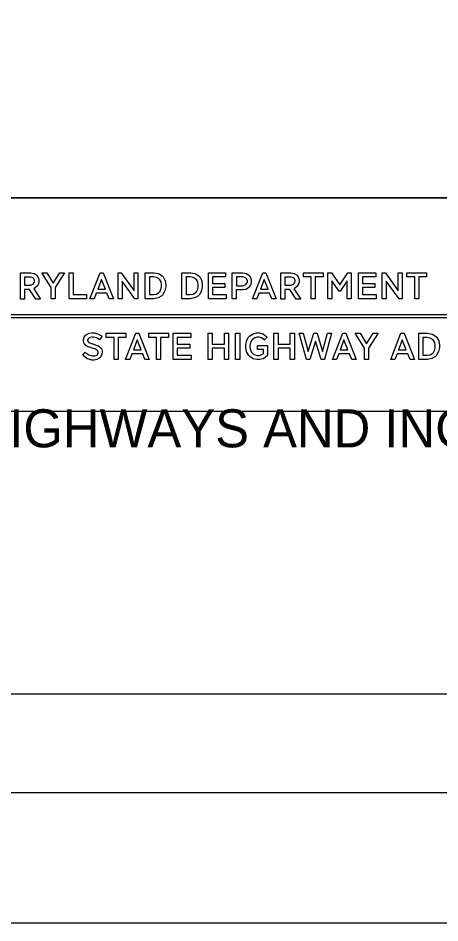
# Model space of a CAD drawing. Extents: x 12.2 to 54.5, y -7.8 to 16.1.
# Drawn here: x 51.346 to 52.376, y -7.78 to -5.573 of the extents above; entities that cross this region are included whole.
import ezdxf

# ---------------------------------------------------------------- set-up
doc = ezdxf.new("R2010")
doc.units = 0
for name, color, linetype in [('BORD-LINE', 7, 'Continuous'), ('MSHA-LOGO', 7, 'Continuous'), ('TTLB-TEXT', 7, 'Continuous'), ('USER-BORD', 7, 'Continuous'), ('USER-LINE', 7, 'Continuous')]:
    doc.layers.add(name, color=color, linetype=linetype)

msp = doc.modelspace()

# ---------------------------------------------------------------- linework, layer by layer
at = {"layer": 'BORD-LINE'}
for p, q in [((54.2173, -6.0121), (49.7444, -6.0121)), ((49.7444, -7.2211), (54.2173, -7.2211))]:
    msp.add_line(p, q, dxfattribs=at)
msp.add_lwpolyline([(46.8431, 2.8902), (54.2173, 2.8902), (54.2173, -7.4629), (46.8431, -7.4629)], close=True, dxfattribs=at)
at = {"layer": 'MSHA-LOGO'}
for points in [[(51.3519, -6.2583), (51.3519, -6.1948), (51.3742, -6.1948), (51.377, -6.1948), (51.3845, -6.1962), (51.3853, -6.1965), (51.3861, -6.1967), (51.3918, -6.2006), (51.3922, -6.2011), (51.3926, -6.2015), (51.3955, -6.2067), (51.3958, -6.2073), (51.3959, -6.2079), (51.3968, -6.2131), (51.3968, -6.2149), (51.3968, -6.2178), (51.3941, -6.2256), (51.3935, -6.2264), (51.3929, -6.2272), (51.3853, -6.233), (51.3843, -6.2333), (51.4013, -6.2586), (51.3892, -6.2586), (51.3739, -6.2353), (51.3617, -6.2353), (51.3617, -6.2586), (51.3519, -6.2586)], [(51.4367, -6.2307), (51.4367, -6.2583), (51.4269, -6.2583), (51.4269, -6.2307), (51.404, -6.1945), (51.4161, -6.1945), (51.4318, -6.2198), (51.4478, -6.1945), (51.4596, -6.1945)], [(51.4707, -6.1945), (51.4805, -6.1945), (51.4805, -6.2478), (51.5129, -6.2478), (51.5129, -6.258), (51.4707, -6.258)], [(51.5466, -6.1945), (51.5542, -6.1945), (51.579, -6.258), (51.5686, -6.258), (51.563, -6.2438), (51.5372, -6.2438), (51.5316, -6.258), (51.5218, -6.258)], [(51.6314, -6.2583), (51.6, -6.2149), (51.6, -6.2583), (51.5905, -6.2583), (51.5905, -6.1948), (51.598, -6.1948), (51.6294, -6.2382), (51.6294, -6.1948), (51.6389, -6.1948), (51.6389, -6.2583)], [(51.6569, -6.1945), (51.6746, -6.1945), (51.6784, -6.1945), (51.6886, -6.1964), (51.6897, -6.1968), (51.6907, -6.1972), (51.6991, -6.203), (51.6998, -6.2037), (51.7004, -6.2044), (51.7048, -6.2126), (51.705, -6.2136), (51.7053, -6.2145), (51.7067, -6.2227), (51.7067, -6.2254), (51.7067, -6.2287), (51.7047, -6.2385), (51.6999, -6.2475), (51.6985, -6.2491), (51.6971, -6.2506), (51.6881, -6.2557), (51.6773, -6.258), (51.6736, -6.258), (51.6569, -6.258)], [(51.7463, -6.1945), (51.7639, -6.1945), (51.7677, -6.1945), (51.7779, -6.1964), (51.779, -6.1968), (51.78, -6.1972), (51.7885, -6.203), (51.7891, -6.2037), (51.7897, -6.2044), (51.7941, -6.2126), (51.7944, -6.2136), (51.7946, -6.2145), (51.796, -6.2227), (51.796, -6.2254), (51.796, -6.2287), (51.794, -6.2385), (51.7892, -6.2475), (51.7878, -6.2491), (51.7864, -6.2506), (51.7775, -6.2557), (51.7666, -6.258), (51.763, -6.258), (51.7463, -6.258)], [(51.8108, -6.1945), (51.8529, -6.1945), (51.8529, -6.2047), (51.8206, -6.2047), (51.8206, -6.2208), (51.851, -6.2208), (51.851, -6.2307), (51.8206, -6.2307), (51.8206, -6.2474), (51.8539, -6.2474), (51.8539, -6.2576), (51.8108, -6.2576)], [(51.869, -6.2583), (51.869, -6.1948), (51.8919, -6.1948), (51.8948, -6.1948), (51.9029, -6.1962), (51.9037, -6.1965), (51.9045, -6.1968), (51.9105, -6.2009), (51.9109, -6.2014), (51.9113, -6.2019), (51.9143, -6.2074), (51.9145, -6.208), (51.9146, -6.2085), (51.9155, -6.2138), (51.9155, -6.2155), (51.9155, -6.2174), (51.9144, -6.2225), (51.9142, -6.2231), (51.9139, -6.2237), (51.9106, -6.2292), (51.9102, -6.2297), (51.9098, -6.2302), (51.9035, -6.2343), (51.9027, -6.2346), (51.9019, -6.2349), (51.8941, -6.2363), (51.8916, -6.2363), (51.8785, -6.2363), (51.8785, -6.258), (51.869, -6.258)], [(51.9439, -6.1945), (51.9515, -6.1945), (51.9763, -6.258), (51.9659, -6.258), (51.9603, -6.2442), (51.9344, -6.2442), (51.9289, -6.2583), (51.9187, -6.2583)], [(51.9875, -6.2583), (51.9875, -6.1948), (52.0097, -6.1948), (52.0125, -6.1948), (52.02, -6.1962), (52.0208, -6.1965), (52.0216, -6.1967), (52.0273, -6.2006), (52.0277, -6.2011), (52.0281, -6.2015), (52.031, -6.2067), (52.0313, -6.2073), (52.0315, -6.2079), (52.0323, -6.2131), (52.0323, -6.2149), (52.0323, -6.2178), (52.0296, -6.2256), (52.029, -6.2264), (52.0284, -6.2272), (52.0208, -6.233), (52.0198, -6.2333), (52.0369, -6.2586), (52.0248, -6.2586), (52.0094, -6.2353), (51.9973, -6.2353), (51.9973, -6.2586), (51.9875, -6.2586)], [(52.0428, -6.1945), (52.0909, -6.1945), (52.0909, -6.2047), (52.0716, -6.2047), (52.0716, -6.258), (52.0617, -6.258), (52.0617, -6.2047), (52.0428, -6.2047)], [(52.1023, -6.1945), (52.1112, -6.1945), (52.1315, -6.2241), (52.1511, -6.1945), (52.1596, -6.1945), (52.1596, -6.258), (52.1498, -6.258), (52.1498, -6.2139), (52.1324, -6.2392), (52.1298, -6.2392), (52.1121, -6.2139), (52.1121, -6.258), (52.1023, -6.258)], [(52.1773, -6.1945), (52.2195, -6.1945), (52.2195, -6.2047), (52.1871, -6.2047), (52.1871, -6.2208), (52.2175, -6.2208), (52.2175, -6.2307), (52.1871, -6.2307), (52.1871, -6.2474), (52.2205, -6.2474), (52.2205, -6.2576), (52.1773, -6.2576)], [(52.2764, -6.2583), (52.245, -6.2149), (52.245, -6.2583), (52.2355, -6.2583), (52.2355, -6.1948), (52.243, -6.1948), (52.2745, -6.2382), (52.2745, -6.1948), (52.284, -6.1948), (52.284, -6.2583)], [(52.2954, -6.1945), (52.3435, -6.1945), (52.3435, -6.2047), (52.3245, -6.2047), (52.3245, -6.258), (52.3147, -6.258), (52.3147, -6.2047), (52.2957, -6.2047), (52.2957, -6.1945)], [(51.3617, -6.205), (51.3617, -6.2244), (51.3745, -6.2244), (51.3767, -6.2244), (51.3828, -6.2222), (51.3833, -6.2218), (51.3838, -6.2214), (51.3866, -6.216), (51.3866, -6.2142), (51.3866, -6.2125), (51.3842, -6.2077), (51.3837, -6.2073), (51.3832, -6.2069), (51.3764, -6.205), (51.3742, -6.205)], [(51.5411, -6.2346), (51.5597, -6.2346), (51.5502, -6.2106)], [(51.6668, -6.205), (51.6668, -6.2478), (51.6743, -6.2478), (51.6767, -6.2478), (51.6841, -6.2463), (51.6901, -6.2428), (51.691, -6.2419), (51.6919, -6.2409), (51.6951, -6.2347), (51.6965, -6.2277), (51.6965, -6.2254), (51.6965, -6.2231), (51.6952, -6.2163), (51.6911, -6.2099), (51.6842, -6.206), (51.677, -6.2047), (51.6746, -6.2047), (51.6668, -6.2047)], [(51.7564, -6.205), (51.7564, -6.2478), (51.7639, -6.2478), (51.7664, -6.2478), (51.7738, -6.2463), (51.7797, -6.2428), (51.7806, -6.2419), (51.7815, -6.2409), (51.7848, -6.2347), (51.7862, -6.2277), (51.7862, -6.2254), (51.7862, -6.2231), (51.7848, -6.2163), (51.7808, -6.2099), (51.7739, -6.206), (51.7667, -6.2047), (51.7643, -6.2047), (51.7564, -6.2047)], [(51.8791, -6.2047), (51.8791, -6.2261), (51.8922, -6.2261), (51.8948, -6.2261), (51.9025, -6.2233), (51.906, -6.2172), (51.906, -6.2152), (51.906, -6.2132), (51.9027, -6.2073), (51.8953, -6.2047), (51.8929, -6.2047)], [(51.938, -6.2346), (51.9567, -6.2346), (51.9472, -6.2106)], [(51.9976, -6.205), (51.9976, -6.2244), (52.0104, -6.2244), (52.0126, -6.2244), (52.0186, -6.2222), (52.0192, -6.2218), (52.0197, -6.2214), (52.0225, -6.216), (52.0225, -6.2142), (52.0225, -6.2125), (52.02, -6.2077), (52.0195, -6.2073), (52.019, -6.2069), (52.0123, -6.205), (52.01, -6.205)], [(51.2136, -6.2962), (53.3302, -6.2962), (53.3302, -6.3041), (51.2136, -6.3041)], [(51.5397, -6.3835), (51.5393, -6.3832), (51.5351, -6.3805), (51.5345, -6.3803), (51.534, -6.3801), (51.5281, -6.3782), (51.5275, -6.3781), (51.5269, -6.3779), (51.5205, -6.376), (51.5199, -6.3758), (51.5192, -6.3756), (51.5134, -6.3729), (51.5128, -6.3726), (51.5122, -6.3723), (51.508, -6.3677), (51.5077, -6.3671), (51.5074, -6.3666), (51.5058, -6.3607), (51.5058, -6.3588), (51.5058, -6.357), (51.5074, -6.3518), (51.5111, -6.3468), (51.5122, -6.3459), (51.5132, -6.3451), (51.5194, -6.342), (51.5262, -6.3408), (51.5285, -6.3408), (51.5316, -6.3408), (51.5412, -6.3432), (51.5495, -6.3486), (51.5508, -6.3501), (51.5454, -6.3582), (51.5442, -6.357), (51.5375, -6.3531), (51.5305, -6.3514), (51.5282, -6.3514), (51.526, -6.3514), (51.5201, -6.353), (51.5195, -6.3533), (51.519, -6.3537), (51.516, -6.3577), (51.516, -6.3591), (51.516, -6.3604), (51.5182, -6.3639), (51.5186, -6.3643), (51.519, -6.3646), (51.5245, -6.367), (51.5253, -6.3671), (51.526, -6.3673), (51.5331, -6.3695), (51.5339, -6.3697), (51.5347, -6.3699), (51.5419, -6.3727), (51.5425, -6.3729), (51.5432, -6.3732), (51.5488, -6.3781), (51.5492, -6.3787), (51.5496, -6.3793), (51.5518, -6.3858), (51.5518, -6.388), (51.5518, -6.3899), (51.5502, -6.3956), (51.5464, -6.4009), (51.5454, -6.4018), (51.5444, -6.4027), (51.5383, -6.4059), (51.5319, -6.4073), (51.5298, -6.4073), (51.5261, -6.4073), (51.5163, -6.4046), (51.5151, -6.4041), (51.5139, -6.4035), (51.5048, -6.3965), (51.5042, -6.3957), (51.5103, -6.388), (51.5115, -6.3895), (51.5192, -6.3949), (51.5278, -6.3973), (51.5307, -6.3973), (51.5327, -6.3973), (51.5382, -6.3957), (51.5387, -6.3954), (51.5392, -6.3951), (51.5416, -6.391), (51.5416, -6.3896), (51.5416, -6.3881), (51.54, -6.3838)], [(51.5611, -6.3418), (51.6096, -6.3418), (51.6096, -6.3524), (51.5905, -6.3524), (51.5905, -6.406), (51.5806, -6.406), (51.5806, -6.352), (51.5614, -6.352), (51.5614, -6.3418)], [(51.6336, -6.3418), (51.6413, -6.3418), (51.6665, -6.406), (51.656, -6.406), (51.6505, -6.3919), (51.6243, -6.3919), (51.6189, -6.406), (51.6087, -6.406)], [(51.6649, -6.3418), (51.7135, -6.3418), (51.7135, -6.3524), (51.6943, -6.3524), (51.6943, -6.406), (51.6844, -6.406), (51.6844, -6.352), (51.6652, -6.352), (51.6652, -6.3418)], [(51.725, -6.3418), (51.7678, -6.3418), (51.7678, -6.3524), (51.7349, -6.3524), (51.7349, -6.3684), (51.7655, -6.3684), (51.7655, -6.3784), (51.7349, -6.3784), (51.7349, -6.3954), (51.7684, -6.3954), (51.7684, -6.406), (51.725, -6.406)], [(51.8499, -6.3787), (51.8199, -6.3787), (51.8199, -6.406), (51.81, -6.406), (51.81, -6.3418), (51.8199, -6.3418), (51.8199, -6.3684), (51.8499, -6.3684), (51.8499, -6.3418), (51.8598, -6.3418), (51.8598, -6.406), (51.8499, -6.406)], [(51.8774, -6.3418), (51.8873, -6.3418), (51.8873, -6.406), (51.8774, -6.406)], [(51.9304, -6.3716), (51.9553, -6.3716), (51.9553, -6.3964), (51.9547, -6.3972), (51.9464, -6.4033), (51.9454, -6.4037), (51.9444, -6.4042), (51.9356, -6.4063), (51.9326, -6.4063), (51.9296, -6.4063), (51.9204, -6.4041), (51.912, -6.3988), (51.9106, -6.3973), (51.9092, -6.3958), (51.9041, -6.3869), (51.902, -6.3769), (51.902, -6.3736), (51.902, -6.3703), (51.9041, -6.3608), (51.9089, -6.3517), (51.9103, -6.3501), (51.9117, -6.3485), (51.9199, -6.3431), (51.9285, -6.3408), (51.9314, -6.3408), (51.9347, -6.3408), (51.9437, -6.3432), (51.9448, -6.3437), (51.9457, -6.3442), (51.9535, -6.3506), (51.954, -6.3514), (51.9473, -6.3585), (51.9465, -6.3573), (51.9409, -6.3534), (51.9342, -6.3517), (51.932, -6.3517), (51.93, -6.3517), (51.9239, -6.3532), (51.9185, -6.3568), (51.9176, -6.3578), (51.9168, -6.3588), (51.9136, -6.3648), (51.9122, -6.3716), (51.9122, -6.3739), (51.9122, -6.3762), (51.9136, -6.3832), (51.917, -6.3892), (51.918, -6.3903), (51.9189, -6.3912), (51.9244, -6.3946), (51.9306, -6.396), (51.9326, -6.396), (51.9359, -6.396), (51.9449, -6.3923), (51.9457, -6.3916), (51.9457, -6.3816), (51.9304, -6.3816)], [(52.0109, -6.3787), (51.9809, -6.3787), (51.9809, -6.406), (51.971, -6.406), (51.971, -6.3418), (51.9809, -6.3418), (51.9809, -6.3684), (52.0109, -6.3684), (52.0109, -6.3418), (52.0208, -6.3418), (52.0208, -6.406), (52.0109, -6.406)], [(52.0946, -6.406), (52.0863, -6.406), (52.0723, -6.3614), (52.0585, -6.406), (52.0502, -6.406), (52.0323, -6.3418), (52.0426, -6.3418), (52.0547, -6.3861), (52.0681, -6.3418), (52.0761, -6.3418), (52.0898, -6.3861), (52.1017, -6.3418), (52.1116, -6.3418)], [(52.1387, -6.3418), (52.1464, -6.3418), (52.1717, -6.406), (52.1611, -6.406), (52.1553, -6.3919), (52.1291, -6.3919), (52.1237, -6.406), (52.1135, -6.406)], [(52.2017, -6.3781), (52.2017, -6.406), (52.1918, -6.406), (52.1918, -6.3781), (52.1688, -6.3418), (52.1812, -6.3418), (52.1972, -6.3675), (52.2135, -6.3418), (52.2253, -6.3418)], [(52.2808, -6.3418), (52.2885, -6.3418), (52.3137, -6.406), (52.3032, -6.406), (52.2977, -6.3919), (52.2716, -6.3919), (52.2661, -6.406), (52.2559, -6.406)], [(52.3249, -6.3418), (52.3428, -6.3418), (52.3465, -6.3418), (52.3568, -6.3439), (52.3578, -6.3443), (52.3589, -6.3447), (52.3674, -6.3506), (52.368, -6.3514), (52.3687, -6.3521), (52.3731, -6.3604), (52.3735, -6.3614), (52.3738, -6.3623), (52.3751, -6.3705), (52.3751, -6.3732), (52.3751, -6.3765), (52.3729, -6.3864), (52.3681, -6.3955), (52.3668, -6.397), (52.3654, -6.3985), (52.3563, -6.4038), (52.3455, -6.406), (52.3418, -6.406), (52.3249, -6.406)], [(52.3348, -6.3524), (52.3348, -6.3957), (52.3425, -6.3957), (52.3449, -6.3957), (52.3524, -6.3942), (52.3585, -6.3906), (52.3594, -6.3896), (52.3604, -6.3886), (52.3636, -6.3824), (52.3648, -6.3755), (52.3648, -6.3732), (52.3648, -6.371), (52.3635, -6.3641), (52.3593, -6.3576), (52.3524, -6.3537), (52.3452, -6.3524), (52.3428, -6.3524)], [(51.6278, -6.3822), (51.6467, -6.3822), (51.6371, -6.3578)], [(52.1327, -6.3822), (52.1515, -6.3822), (52.1419, -6.3578)], [(52.2751, -6.3822), (52.2939, -6.3822), (52.2843, -6.3578)]]:
    msp.add_lwpolyline(points, close=True, dxfattribs=at)
at = {"layer": 'USER-BORD'}
msp.add_lwpolyline([(54.5342, 3.2202), (46.0342, 3.2202), (46.0342, -7.7798), (54.5342, -7.7798)], close=True, dxfattribs=at)
at = {"layer": 'USER-LINE'}
msp.add_lwpolyline([(53.4665, -6.5328), (50.4953, -6.5328), (50.4953, -6.0121), (53.4665, -6.0121)], close=True, dxfattribs=at)

# ---------------------------------------------------------------- texts
at = {"layer": 'TTLB-TEXT'}
msp.add_text('STANDARDS FOR HIGHWAYS AND INCIDENTAL STRUCTURES', height=0.09269, rotation=360, dxfattribs=at).set_placement((50.1402, -6.6201))

doc.saveas('drawing.dxf')
